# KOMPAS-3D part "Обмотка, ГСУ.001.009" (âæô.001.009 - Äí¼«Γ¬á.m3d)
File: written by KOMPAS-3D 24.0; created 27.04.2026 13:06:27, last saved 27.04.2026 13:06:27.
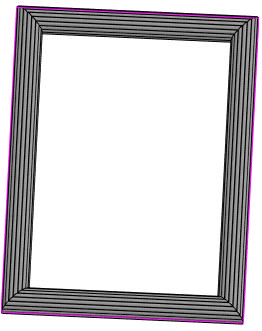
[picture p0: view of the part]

Document properties: Автор: User7; Полное имя файла: C:\Users\User7\Desktop\Двигатель мясорубки\ГСУ.001.009 - Обмотка.m3d

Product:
- Part/product: Обмотка  | designation ГСУ.001.009
    Масса: 0.009785

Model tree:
1. Эскиз:1
2. Эскиз:2
3. Элемент по траектории:1
     Длина траектории = 151.8

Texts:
  ГСУ.001.009
  Шаг 2
  Шаг 1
